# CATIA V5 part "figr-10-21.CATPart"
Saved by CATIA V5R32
Part number: Part1
Bounding box of the stored display mesh (mm): x -60 to 60, y -90 to 70, z -46.082 to 16.155
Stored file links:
  D:\PROJECTS\Project 2022\CATIA V5 6R 2022\Resources\Part Files\c10_catia_v5_6r2022_prt\c10_catia_v5_6r2022_prt\figr-10-21.CATPart
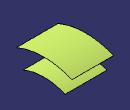
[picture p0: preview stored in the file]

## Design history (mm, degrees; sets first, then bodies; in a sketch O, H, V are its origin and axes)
Set1
  Sketch1 on yz-plane, origin (0, 0, 0), H (0, 1, 0), V (0, 0, 1)
    arc A1 centre (-10, -190) radius 206.1553 from (-90, 0) to (70, 0) cw
  Extrude1: Element1 Sketch1, Lim1 60, Lim2 60, Direction yz-plane
  Offset1: Offset Extrude1, Length 50
Body1 (main body)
